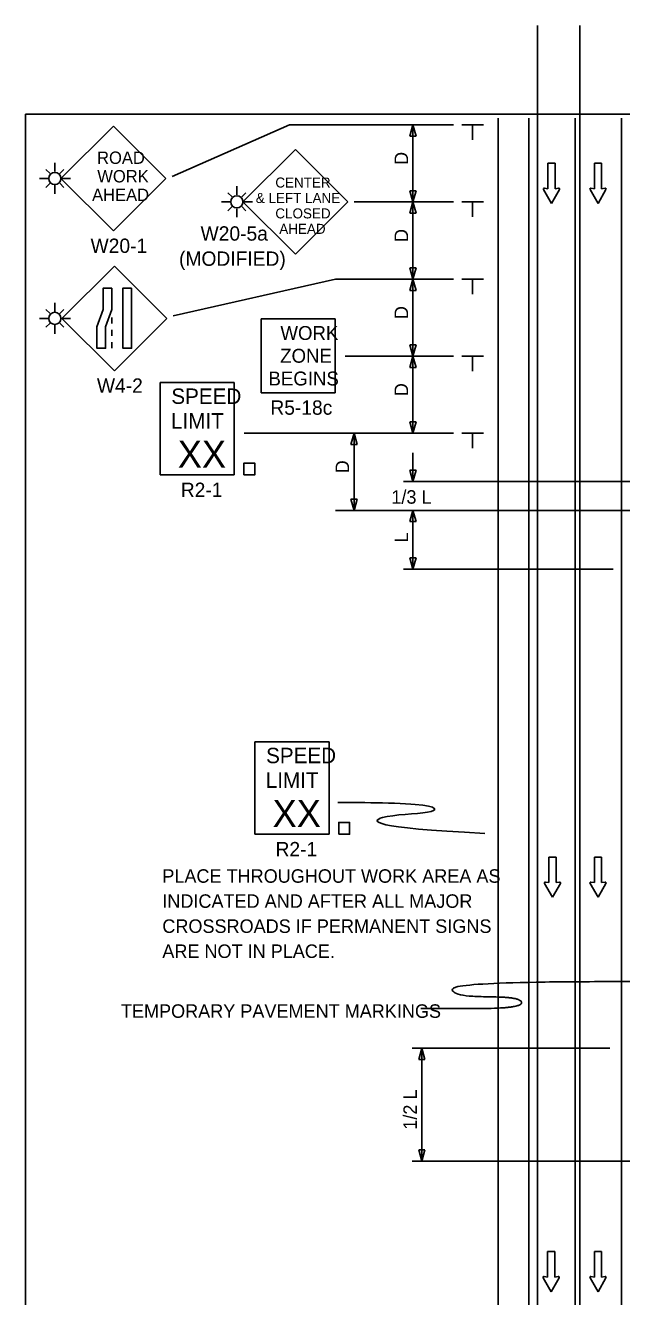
# Model space of a CAD drawing. Extents: x 16723 to 18475, y 7015 to 8267.
# Drawn here: x 16723 to 17032, y 7603 to 8262 of the extents above; entities that cross this region are included whole.
import ezdxf

# ---------------------------------------------------------------- set-up
doc = ezdxf.new("R2010")
doc.units = 0
for name, color, linetype in [('ALI_LEGAL_EX', 7, 'Continuous'), ('BORDER', 7, 'Continuous'), ('MT_SCRATCH_LEVEL_E', 7, 'Continuous'), ('PAVT_EDGE_EX', 7, 'Continuous'), ('TRAFFIC_SIGNS_PR', 7, 'Continuous'), ('TYPICAL_TEXT_DIMEN_PR', 7, 'Continuous')]:
    doc.layers.add(name, color=color, linetype=linetype)

msp = doc.modelspace()

# ---------------------------------------------------------------- linework, layer by layer
at = {"layer": 'ALI_LEGAL_EX'}
for p, q in [((17007.71, 7341.97), (17007.71, 8214.17)), ((17031.71, 7341.97), (17031.71, 8214.17))]:
    msp.add_line(p, q, dxfattribs=at)
for points in [[(17007.71, 8141.97), (17007.71, 8166.97)], [(17031.71, 8141.97), (17031.71, 8166.97)], [(17007.71, 8041.97), (17007.71, 8066.97)], [(17031.71, 8041.97), (17031.71, 8066.97)], [(17007.71, 7941.97), (17007.71, 7966.97)], [(17007.71, 7841.97), (17007.71, 7866.97)], [(17031.71, 7841.97), (17031.71, 7866.97)], [(17007.71, 7741.97), (17007.71, 7766.97)], [(17031.71, 7741.97), (17031.71, 7766.97)], [(17007.71, 7641.97), (17007.71, 7666.97)], [(17031.71, 7641.97), (17031.71, 7666.97)]]:
    msp.add_lwpolyline(points, dxfattribs=at)
at = {"layer": 'BORDER'}
for p, q in [((16722.75, 7216.25), (16722.75, 8216.25)), ((16722.75, 8216.25), (17422.75, 8216.25))]:
    msp.add_line(p, q, dxfattribs=at)
at = {"layer": 'MT_SCRATCH_LEVEL_E'}
for p, q in [((16997.31, 8190.82), (16993.57, 8190.82)), ((16993.57, 8190.82), (16993.57, 8177.56)), ((16997.31, 8190.82), (16993.57, 8190.82)), ((16993.57, 8190.82), (16993.57, 8177.56)), ((16997.31, 8177.56), (16997.31, 8190.82)), ((16997.31, 8177.56), (16997.31, 8190.82)), ((17021.38, 8190.82), (17017.64, 8190.82)), ((17017.64, 8190.82), (17017.64, 8177.56)), ((17021.38, 8190.82), (17017.64, 8190.82)), ((17017.64, 8190.82), (17017.64, 8177.56)), ((17021.38, 8190.82), (17017.64, 8190.82)), ((17017.64, 8190.82), (17017.64, 8177.56)), ((17021.38, 8190.82), (17017.64, 8190.82)), ((17017.64, 8190.82), (17017.64, 8177.56)), ((17021.38, 8177.56), (17021.38, 8190.82)), ((17021.38, 8177.56), (17021.38, 8190.82)), ((17021.38, 8177.56), (17021.38, 8190.82)), ((17021.38, 8177.56), (17021.38, 8190.82)), ((16991.31, 8177.19), (16995.46, 8169.95)), ((16991.31, 8177.19), (16995.46, 8169.95)), ((16993.57, 8177.56), (16991.79, 8177.88)), ((16993.57, 8177.56), (16991.79, 8177.88)), ((16995.46, 8169.95), (16999.57, 8177.19)), ((16995.46, 8169.95), (16999.57, 8177.19)), ((16999.09, 8177.88), (16997.31, 8177.56)), ((16999.09, 8177.88), (16997.31, 8177.56)), ((17015.38, 8177.19), (17019.53, 8169.95)), ((17015.38, 8177.19), (17019.53, 8169.95)), ((17015.38, 8177.19), (17019.53, 8169.95)), ((17015.38, 8177.19), (17019.53, 8169.95)), ((17017.64, 8177.56), (17015.86, 8177.88)), ((17017.64, 8177.56), (17015.86, 8177.88)), ((17017.64, 8177.56), (17015.86, 8177.88)), ((17017.64, 8177.56), (17015.86, 8177.88)), ((17019.53, 8169.95), (17023.64, 8177.19)), ((17019.53, 8169.95), (17023.64, 8177.19)), ((17019.53, 8169.95), (17023.64, 8177.19)), ((17019.53, 8169.95), (17023.64, 8177.19)), ((17023.16, 8177.88), (17021.38, 8177.56)), ((17023.16, 8177.88), (17021.38, 8177.56)), ((17023.16, 8177.88), (17021.38, 8177.56)), ((17023.16, 8177.88), (17021.38, 8177.56)), ((16997.81, 7830.82), (16994.07, 7830.82)), ((16994.07, 7830.82), (16994.07, 7817.56)), ((16997.81, 7830.82), (16994.07, 7830.82)), ((16994.07, 7830.82), (16994.07, 7817.56)), ((16997.81, 7817.56), (16997.81, 7830.82)), ((16997.81, 7817.56), (16997.81, 7830.82)), ((17021.38, 7830.82), (17017.64, 7830.82)), ((17017.64, 7830.82), (17017.64, 7817.56)), ((17021.38, 7830.82), (17017.64, 7830.82)), ((17017.64, 7830.82), (17017.64, 7817.56)), ((17021.38, 7817.56), (17021.38, 7830.82)), ((17021.38, 7817.56), (17021.38, 7830.82)), ((16991.82, 7817.19), (16995.96, 7809.95)), ((16991.82, 7817.19), (16995.96, 7809.95)), ((16994.07, 7817.56), (16992.3, 7817.88)), ((16994.07, 7817.56), (16992.3, 7817.88)), ((16995.96, 7809.95), (17000.07, 7817.19)), ((16995.96, 7809.95), (17000.07, 7817.19)), ((16999.59, 7817.88), (16997.81, 7817.56)), ((16999.59, 7817.88), (16997.81, 7817.56)), ((17015.38, 7817.19), (17019.53, 7809.95)), ((17015.38, 7817.19), (17019.53, 7809.95)), ((17017.64, 7817.56), (17015.86, 7817.88)), ((17017.64, 7817.56), (17015.86, 7817.88)), ((17019.53, 7809.95), (17023.64, 7817.19)), ((17019.53, 7809.95), (17023.64, 7817.19)), ((17023.16, 7817.88), (17021.38, 7817.56)), ((17023.16, 7817.88), (17021.38, 7817.56)), ((16997.13, 7626.2), (16993.38, 7626.2)), ((16993.38, 7626.2), (16993.38, 7612.95)), ((16997.13, 7626.2), (16993.38, 7626.2)), ((16993.38, 7626.2), (16993.38, 7612.95)), ((16997.13, 7612.95), (16997.13, 7626.2)), ((16997.13, 7612.95), (16997.13, 7626.2)), ((17021.38, 7626.2), (17017.64, 7626.2)), ((17017.64, 7626.2), (17017.64, 7612.95)), ((17021.38, 7626.2), (17017.64, 7626.2)), ((17017.64, 7626.2), (17017.64, 7612.95)), ((17021.38, 7612.95), (17021.38, 7626.2)), ((17021.38, 7612.95), (17021.38, 7626.2)), ((16991.13, 7612.58), (16995.27, 7605.34)), ((16991.13, 7612.58), (16995.27, 7605.34)), ((16993.38, 7612.95), (16991.61, 7613.26)), ((16993.38, 7612.95), (16991.61, 7613.26)), ((16995.27, 7605.34), (16999.39, 7612.58)), ((16995.27, 7605.34), (16999.39, 7612.58)), ((16998.9, 7613.26), (16997.13, 7612.95)), ((16998.9, 7613.26), (16997.13, 7612.95)), ((17015.38, 7612.58), (17019.53, 7605.34)), ((17015.38, 7612.58), (17019.53, 7605.34)), ((17017.64, 7612.95), (17015.86, 7613.26)), ((17017.64, 7612.95), (17015.86, 7613.26)), ((17019.53, 7605.34), (17023.64, 7612.58)), ((17019.53, 7605.34), (17023.64, 7612.58)), ((17023.16, 7613.26), (17021.38, 7612.95)), ((17023.16, 7613.26), (17021.38, 7612.95))]:
    msp.add_line(p, q, dxfattribs=at)
for centre, start, end in [((16991.72, 8177.42), 80.03619, 209.77312), ((16991.72, 8177.42), 80.03619, 209.77312), ((16999.16, 8177.42), 330.42484, 99.96381), ((16999.16, 8177.42), 330.42484, 99.96381), ((17015.79, 8177.42), 80.03619, 209.77312), ((17015.79, 8177.42), 80.03619, 209.77312), ((17015.79, 8177.42), 80.03619, 209.77312), ((17015.79, 8177.42), 80.03619, 209.77312), ((17023.23, 8177.42), 330.42484, 99.96381), ((17023.23, 8177.42), 330.42484, 99.96381), ((17023.23, 8177.42), 330.42484, 99.96381), ((17023.23, 8177.42), 330.42484, 99.96381), ((16992.23, 7817.42), 80.03619, 209.77312), ((16992.23, 7817.42), 80.03619, 209.77312), ((16999.67, 7817.42), 330.42484, 99.96381), ((16999.67, 7817.42), 330.42484, 99.96381), ((17015.79, 7817.42), 80.03619, 209.77312), ((17015.79, 7817.42), 80.03619, 209.77312), ((17023.23, 7817.42), 330.42484, 99.96381), ((17023.23, 7817.42), 330.42484, 99.96381), ((16991.54, 7612.8), 80.03619, 209.77312), ((16991.54, 7612.8), 80.03619, 209.77312), ((16998.98, 7612.8), 330.42484, 99.96381), ((16998.98, 7612.8), 330.42484, 99.96381), ((17015.79, 7612.8), 80.03619, 209.77312), ((17015.79, 7612.8), 80.03619, 209.77312), ((17023.23, 7612.8), 330.42484, 99.96381), ((17023.23, 7612.8), 330.42484, 99.96381)]:
    msp.add_arc(centre, 0.463, start, end, dxfattribs=at)
at = {"layer": 'PAVT_EDGE_EX'}
for p, q in [((16988.15, 8262.34), (16988.15, 7433.15)), ((17010.15, 8262.34), (17010.15, 7433.15)), ((16967.71, 8214.17), (16967.71, 7352.81)), ((16983.71, 8214.17), (16983.71, 7352.81))]:
    msp.add_line(p, q, dxfattribs=at)
at = {"layer": 'TRAFFIC_SIGNS_PR'}
for p, q in [((16768.35, 8210.13), (16741.16, 8182.94)), ((16795.53, 8182.94), (16768.35, 8210.13)), ((16862.66, 8198), (16835.47, 8170.81)), ((16889.85, 8170.81), (16862.66, 8198)), ((16735.49, 8185.46), (16733.39, 8187.56)), ((16738.01, 8186.5), (16738.01, 8191)), ((16740.52, 8185.46), (16742.63, 8187.56)), ((16734.85, 8182.94), (16730.01, 8182.94)), ((16735.49, 8180.43), (16733.39, 8178.32)), ((16738.01, 8174.98), (16738.01, 8179.39)), ((16740.52, 8180.43), (16742.63, 8178.32)), ((16741.16, 8182.94), (16768.35, 8155.76)), ((16741.16, 8182.94), (16746.04, 8182.94)), ((16768.35, 8155.76), (16795.53, 8182.94)), ((16832.32, 8174.36), (16832.32, 8178.87)), ((16829.81, 8173.32), (16827.7, 8175.43)), ((16834.83, 8173.32), (16836.94, 8175.43)), ((16829.17, 8170.81), (16824.33, 8170.81)), ((16829.81, 8168.3), (16827.7, 8166.19)), ((16832.32, 8162.84), (16832.32, 8167.25)), ((16834.83, 8168.3), (16836.94, 8166.19)), ((16835.47, 8170.81), (16862.66, 8143.62)), ((16835.47, 8170.81), (16840.35, 8170.81)), ((16835.47, 8170.81), (16862.66, 8143.62)), ((16862.66, 8143.62), (16889.85, 8170.81)), ((16768.85, 8137.48), (16741.69, 8110.33)), ((16796, 8110.33), (16768.85, 8137.48)), ((16735.49, 8112.84), (16733.38, 8114.95)), ((16738, 8113.89), (16738, 8118.39)), ((16740.52, 8112.84), (16742.62, 8114.95)), ((16734.85, 8110.33), (16730.01, 8110.33)), ((16735.49, 8107.82), (16733.38, 8105.71)), ((16738, 8102.37), (16738, 8106.78)), ((16740.52, 8107.82), (16742.62, 8105.71)), ((16741.16, 8110.33), (16746.04, 8110.33)), ((16741.69, 8110.33), (16768.85, 8083.18)), ((16767.6, 8110.82), (16767.6, 8107.62)), ((16768.85, 8083.18), (16796, 8110.33)), ((16844.9, 8071.78), (16844.9, 8110.18)), ((16844.9, 8110.18), (16883.3, 8110.18)), ((16883.3, 8071.78), (16883.3, 8110.18)), ((16767.6, 8104.42), (16767.6, 8101.22)), ((16767.6, 8098.02), (16767.6, 8094.82)), ((16792.6, 8077.1), (16831, 8077.1)), ((16792.6, 8029.1), (16792.6, 8077.1)), ((16831, 8029.1), (16831, 8077.1)), ((16844.9, 8071.78), (16883.3, 8071.78)), ((16792.6, 8029.1), (16831, 8029.1)), ((16841.71, 7890.67), (16880.11, 7890.67)), ((16841.71, 7842.67), (16841.71, 7890.67)), ((16880.11, 7842.67), (16880.11, 7890.67)), ((16841.71, 7842.67), (16880.11, 7842.67))]:
    msp.add_line(p, q, dxfattribs=at)
for points in [[(16767.6, 8126.07), (16767.6, 8114.88), (16764.26, 8106), (16764.26, 8094.82), (16759.76, 8094.82), (16759.76, 8106), (16763.11, 8114.88), (16763.11, 8126.07)], [(16777.74, 8126.07), (16777.74, 8094.82), (16773.24, 8094.82), (16773.24, 8126.07)], [(16836.02, 8029.1), (16841.61, 8029.1), (16841.61, 8035.27), (16836.02, 8035.27)], [(16885.13, 7842.67), (16890.72, 7842.67), (16890.72, 7848.85), (16885.13, 7848.85)]]:
    msp.add_lwpolyline(points, close=True, dxfattribs=at)
for centre in [(16738.01, 8182.94), (16832.32, 8170.81), (16738, 8110.33)]:
    msp.add_circle(centre, 3.15, dxfattribs=at)
at = {"layer": 'TYPICAL_TEXT_DIMEN_PR'}
for p, q in [((16798.77, 8183.94), (16859.68, 8210.73)), ((16859.68, 8210.73), (16944.61, 8210.73)), ((16922.04, 8204.87), (16923.61, 8210.73)), ((16922.04, 8204.87), (16923.61, 8210.73)), ((16923.61, 8204.87), (16922.04, 8204.87)), ((16923.61, 8204.87), (16922.04, 8204.87)), ((16923.61, 8210.73), (16925.18, 8204.87)), ((16923.61, 8210.73), (16925.18, 8204.87)), ((16923.61, 8170.73), (16923.61, 8210.73)), ((16925.18, 8204.87), (16923.61, 8204.87)), ((16925.18, 8204.87), (16923.61, 8204.87)), ((16948.86, 8210.73), (16960.11, 8210.73)), ((16948.86, 8210.73), (16960.11, 8210.73)), ((16954.49, 8210.73), (16954.49, 8202.94)), ((16954.49, 8210.73), (16954.49, 8202.94)), ((16923.61, 8170.73), (16922.04, 8176.59)), ((16922.04, 8176.59), (16923.61, 8176.59)), ((16923.61, 8170.73), (16922.04, 8176.59)), ((16922.04, 8176.59), (16923.61, 8176.59)), ((16923.61, 8176.59), (16925.18, 8176.59)), ((16925.18, 8176.59), (16923.61, 8170.73)), ((16923.61, 8176.59), (16925.18, 8176.59)), ((16925.18, 8176.59), (16923.61, 8170.73)), ((16893.06, 8170.73), (16944.61, 8170.73)), ((16922.04, 8164.87), (16923.61, 8170.73)), ((16922.04, 8164.87), (16923.61, 8170.73)), ((16923.61, 8170.73), (16925.18, 8164.87)), ((16923.61, 8130.73), (16923.61, 8170.73)), ((16923.61, 8170.73), (16925.18, 8164.87)), ((16948.86, 8170.73), (16960.11, 8170.73)), ((16954.49, 8170.73), (16954.49, 8162.94)), ((16923.61, 8164.87), (16922.04, 8164.87)), ((16923.61, 8164.87), (16922.04, 8164.87)), ((16925.18, 8164.87), (16923.61, 8164.87)), ((16925.18, 8164.87), (16923.61, 8164.87)), ((16923.61, 8130.73), (16922.04, 8136.59)), ((16922.04, 8136.59), (16923.61, 8136.59)), ((16923.61, 8130.73), (16922.04, 8136.59)), ((16922.04, 8136.59), (16923.61, 8136.59)), ((16923.61, 8136.59), (16925.18, 8136.59)), ((16925.18, 8136.59), (16923.61, 8130.73)), ((16923.61, 8136.59), (16925.18, 8136.59)), ((16925.18, 8136.59), (16923.61, 8130.73)), ((16883.52, 8130.73), (16799.32, 8111.7)), ((16883.52, 8130.73), (16944.61, 8130.73)), ((16922.04, 8124.87), (16923.61, 8130.73)), ((16923.61, 8130.73), (16925.18, 8124.87)), ((16923.61, 8090.73), (16923.61, 8130.73)), ((16948.86, 8130.73), (16960.11, 8130.73)), ((16954.49, 8130.73), (16954.49, 8122.94)), ((16923.61, 8124.87), (16922.04, 8124.87)), ((16925.18, 8124.87), (16923.61, 8124.87)), ((16923.61, 8090.73), (16922.04, 8096.59)), ((16922.04, 8096.59), (16923.61, 8096.59)), ((16923.61, 8090.73), (16922.04, 8096.59)), ((16922.04, 8096.59), (16923.61, 8096.59)), ((16923.61, 8096.59), (16925.18, 8096.59)), ((16925.18, 8096.59), (16923.61, 8090.73)), ((16923.61, 8096.59), (16925.18, 8096.59)), ((16925.18, 8096.59), (16923.61, 8090.73)), ((16888.47, 8090.73), (16944.61, 8090.73)), ((16922.04, 8084.87), (16923.61, 8090.73)), ((16923.61, 8050.73), (16923.61, 8090.73)), ((16923.61, 8090.73), (16925.18, 8084.87)), ((16948.86, 8090.73), (16960.11, 8090.73)), ((16954.49, 8090.73), (16954.49, 8082.94)), ((16923.61, 8084.87), (16922.04, 8084.87)), ((16925.18, 8084.87), (16923.61, 8084.87)), ((16923.61, 8050.73), (16922.04, 8056.59)), ((16922.04, 8056.59), (16923.61, 8056.59)), ((16923.61, 8050.73), (16922.04, 8056.59)), ((16922.04, 8056.59), (16923.61, 8056.59)), ((16923.61, 8056.59), (16925.18, 8056.59)), ((16925.18, 8056.59), (16923.61, 8050.73)), ((16923.61, 8056.59), (16925.18, 8056.59)), ((16925.18, 8056.59), (16923.61, 8050.73)), ((16836.17, 8050.73), (16944.61, 8050.73)), ((16891.47, 8044.87), (16893.04, 8050.73)), ((16893.04, 8050.73), (16894.61, 8044.87)), ((16893.04, 8010.73), (16893.04, 8050.73)), ((16948.86, 8050.73), (16960.11, 8050.73)), ((16954.49, 8050.73), (16954.49, 8042.94)), ((16893.04, 8044.87), (16891.47, 8044.87)), ((16894.61, 8044.87), (16893.04, 8044.87)), ((16923.61, 8040.57), (16923.61, 8025.65)), ((16923.61, 8025.65), (16922.04, 8031.51)), ((16922.04, 8031.51), (16923.61, 8031.51)), ((16923.61, 8025.65), (16922.04, 8031.51)), ((16922.04, 8031.51), (16923.61, 8031.51)), ((16923.61, 8031.51), (16925.18, 8031.51)), ((16925.18, 8031.51), (16923.61, 8025.65)), ((16923.61, 8031.51), (16925.18, 8031.51)), ((16925.18, 8031.51), (16923.61, 8025.65)), ((16918.61, 8025.65), (17020.47, 8025.65)), ((16918.61, 8025.65), (17068.84, 8025.65)), ((16893.04, 8010.73), (16891.47, 8016.59)), ((16891.47, 8016.59), (16893.04, 8016.59)), ((16893.04, 8016.59), (16894.61, 8016.59)), ((16894.61, 8016.59), (16893.04, 8010.73)), ((17024.53, 8010.73), (16883.52, 8010.73)), ((17024.53, 8010.73), (16883.52, 8010.73)), ((17047.93, 8010.73), (16893.04, 8010.73)), ((17024.53, 8010.73), (16893.04, 8010.73)), ((16922.04, 8004.87), (16923.61, 8010.73)), ((16923.61, 7980.19), (16923.61, 8010.73)), ((16923.61, 8010.73), (16925.18, 8004.87)), ((16923.61, 8004.87), (16922.04, 8004.87)), ((16925.18, 8004.87), (16923.61, 8004.87)), ((16923.61, 7980.19), (16922.04, 7986.06)), ((16922.04, 7986.06), (16923.61, 7986.06)), ((16923.61, 7986.06), (16925.18, 7986.06)), ((16925.18, 7986.06), (16923.61, 7980.19)), ((16918.61, 7980.19), (17027.31, 7980.19)), ((17028.75, 7766.24), (17053.75, 7766.24)), ((16923.21, 7731.67), (17025.7, 7731.67)), ((16923.21, 7731.67), (17025.7, 7731.67)), ((16926.64, 7725.81), (16928.21, 7731.67)), ((16928.21, 7673.02), (16928.21, 7731.67)), ((16928.21, 7731.67), (16929.78, 7725.81)), ((16928.21, 7725.81), (16926.64, 7725.81)), ((16929.78, 7725.81), (16928.21, 7725.81)), ((16928.21, 7673.02), (16926.64, 7678.89)), ((16926.64, 7678.89), (16928.21, 7678.89)), ((16928.21, 7678.89), (16929.78, 7678.89)), ((16929.78, 7678.89), (16928.21, 7673.02)), ((16923.21, 7673.03), (17071.46, 7673.03))]:
    msp.add_line(p, q, dxfattribs=at)
for points, degree in [([(16960.84, 7843.12), (16901.02, 7846.03), (16902.3, 7853.04), (16936.9, 7853.04), (16936.9, 7859.19), (16888.6, 7859.19), (16884.67, 7859.19)], 3), ([(17028.75, 7766.24), (16943.97, 7766.24), (16943.97, 7758.36), (16979.93, 7758.36), (16979.93, 7752.21), (16931.64, 7752.21), (16927.7, 7752.21)], 2)]:
    msp.add_open_spline(points, degree=degree, dxfattribs=at)

# ---------------------------------------------------------------- texts
at = {"layer": 'TRAFFIC_SIGNS_PR'}
for s, height, p in [('ROAD', 6.408, (16759.88, 8190.49)), ('WORK', 6.408, (16759.99, 8180.88)), ('CENTER', 5.206, (16852.28, 8178.22)), ('AHEAD', 6.408, (16757.29, 8171.26)), ('& LEFT LANE', 5.2065, (16842.14, 8170.21)), ('CLOSED', 5.206, (16852.28, 8162.2)), ('AHEAD', 5.206, (16854.31, 8154.19)), ('W20-5a', 7.449, (16813.52, 8150.66)), ('W20-1', 7.449, (16756.5, 8144.3)), ('(MODIFIED)', 7.449, (16802.36, 8137.61)), ('WORK', 7.217, (16854.9, 8099.14)), ('ZONE', 7.217, (16854.78, 8087.33)), ('BEGINS', 7.217, (16848.71, 8075.52)), ('W4-2', 7.44, (16759.8, 8071.74)), ('SPEED', 8, (16798.37, 8065.96)), ('R5-18c', 7.44, (16849.71, 8060.34)), ('LIMIT', 8, (16798.21, 8053.16)), ('XX', 14.031, (16801.71, 8032.86)), ('R2-1', 7.44, (16803.28, 8017.66)), ('SPEED', 8, (16847.48, 7879.54)), ('LIMIT', 8, (16847.32, 7866.74)), ('XX', 14.031, (16850.83, 7846.43)), ('R2-1', 7.44, (16852.39, 7831.23)), ('PLACE THROUGHOUT WORK AREA AS', 7, (16793.69, 7817.5)), ('INDICATED AND AFTER ALL MAJOR', 7, (16793.69, 7804.5)), ('CROSSROADS IF PERMANENT SIGNS', 7, (16793.69, 7791.5)), ('ARE NOT IN PLACE.', 7, (16793.69, 7778.5))]:
    msp.add_text(s, height=height, dxfattribs=at).set_placement(p)
at = {"layer": 'TYPICAL_TEXT_DIMEN_PR'}
for s, p in [('D', (16921.06, 8189.95)), ('D', (16921.06, 8149.95)), ('D', (16921.06, 8109.95)), ('D', (16921.06, 8069.95)), ('D', (16890.48, 8029.95)), ('L', (16921.06, 7994.06)), ('1/2 L', (16925.65, 7689.39))]:
    msp.add_text(s, height=7, rotation=90, dxfattribs=at).set_placement(p)
for s, p in [('1/3 L', (16912.4, 8014.18)), ('1/3 L', (16912.4, 8014.18)), ('TEMPORARY PAVEMENT MARKINGS', (16772.23, 7747.43))]:
    msp.add_text(s, height=7, dxfattribs=at).set_placement(p)

doc.saveas('drawing.dxf')
